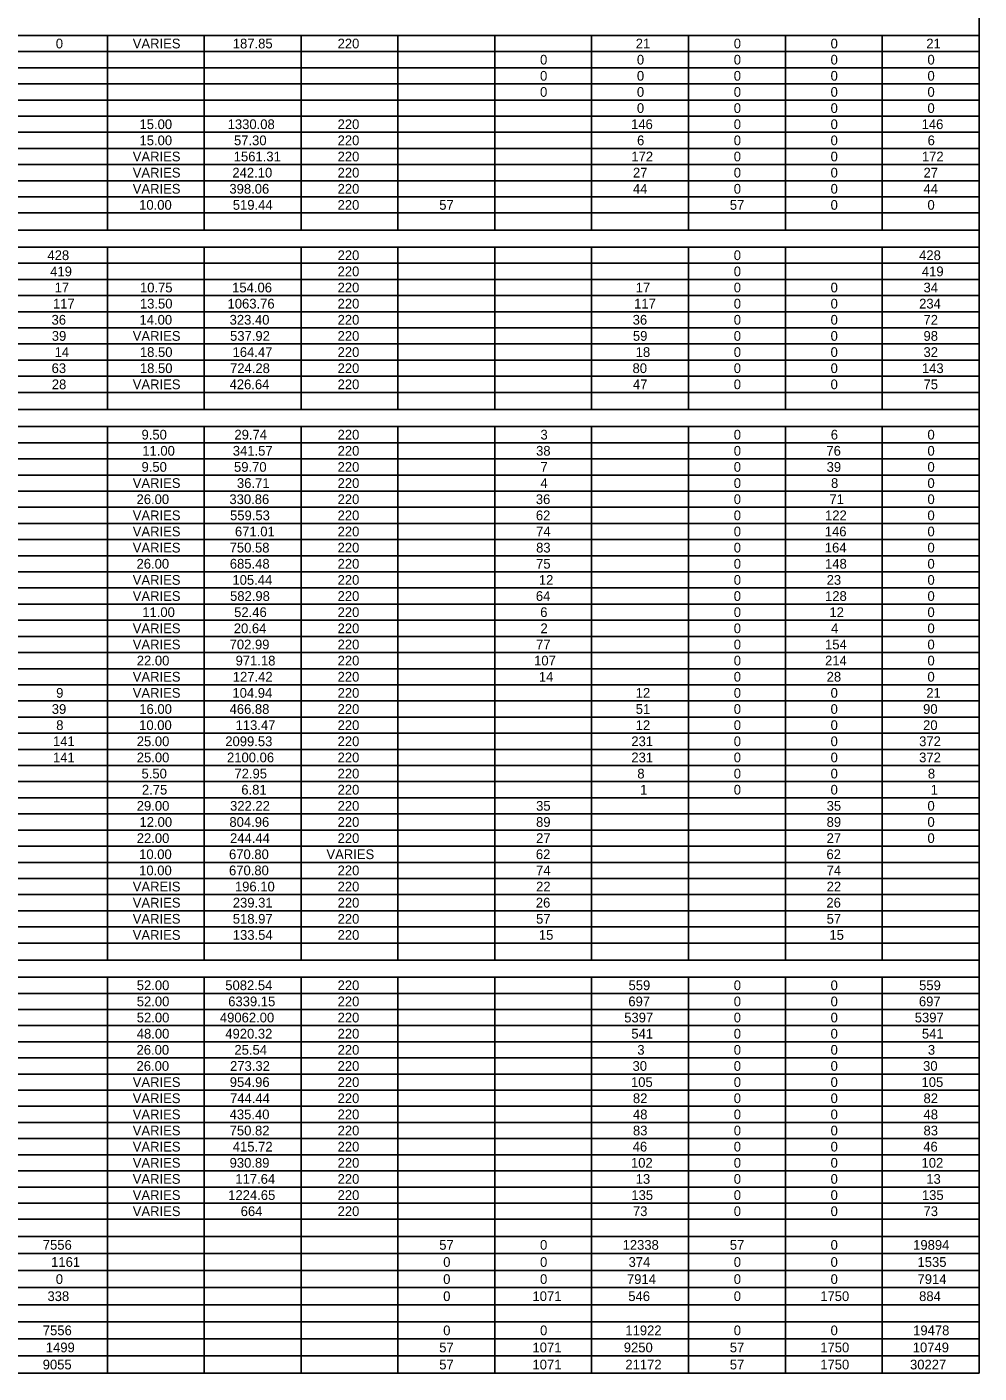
# Model space of a CAD drawing. Extents: x 1226590 to 1228573, y 151304 to 154224.
# Drawn here: x 1228084 to 1228573, y 152628 to 153319 of the extents above; entities that cross this region are included whole.
import ezdxf

# ---------------------------------------------------------------- set-up
doc = ezdxf.new("R2010")
doc.units = 0
doc.layers.add('R_Dimension', color=7, linetype='Continuous')

msp = doc.modelspace()

# ---------------------------------------------------------------- linework, layer by layer
at = {"layer": 'R_Dimension'}
for p, q in [((1228572.93, 152627.62), (1228572.93, 154214.43)), ((1226590.27, 153314.5), (1228572.93, 153314.5)), ((1228125.41, 153214.57), (1228125.41, 153314.5)), ((1228175.13, 153214.57), (1228175.13, 153314.5)), ((1228224.86, 153214.57), (1228224.86, 153314.5)), ((1228274.58, 153214.57), (1228274.58, 153314.5)), ((1228324.31, 153214.57), (1228324.31, 153314.5)), ((1228374.03, 153214.57), (1228374.03, 153314.5)), ((1228423.76, 153214.57), (1228423.76, 153314.5)), ((1228473.48, 153214.57), (1228473.48, 153314.5)), ((1228523.21, 153214.57), (1228523.21, 153314.5)), ((1226590.27, 153306.22), (1228572.93, 153306.22)), ((1226590.27, 153297.93), (1228572.93, 153297.93)), ((1226590.27, 153289.64), (1228572.93, 153289.64)), ((1226590.27, 153281.35), (1228572.93, 153281.35)), ((1226590.27, 153273.07), (1228572.93, 153273.07)), ((1226590.27, 153264.78), (1228572.93, 153264.78)), ((1226590.27, 153256.49), (1228572.93, 153256.49)), ((1226590.27, 153248.2), (1228572.93, 153248.2)), ((1226590.27, 153239.92), (1228572.93, 153239.92)), ((1226590.27, 153231.63), (1228572.93, 153231.63)), ((1226590.27, 153223.34), (1228572.93, 153223.34)), ((1226590.27, 153214.57), (1228572.93, 153214.57)), ((1226590.27, 153205.79), (1228572.93, 153205.79)), ((1228125.41, 153122.43), (1228125.41, 153205.79)), ((1228175.13, 153122.43), (1228175.13, 153205.79)), ((1228224.86, 153122.43), (1228224.86, 153205.79)), ((1228274.58, 153122.43), (1228274.58, 153205.79)), ((1228324.31, 153122.43), (1228324.31, 153205.79)), ((1228374.03, 153122.43), (1228374.03, 153205.79)), ((1228423.76, 153122.43), (1228423.76, 153205.79)), ((1228473.48, 153122.43), (1228473.48, 153205.79)), ((1228523.21, 153122.43), (1228523.21, 153205.79)), ((1226590.27, 153197.5), (1228572.93, 153197.5)), ((1226590.27, 153189.22), (1228572.93, 153189.22)), ((1226590.27, 153180.93), (1228572.93, 153180.93)), ((1226590.27, 153172.64), (1228572.93, 153172.64)), ((1226590.27, 153164.35), (1228572.93, 153164.35)), ((1226590.27, 153156.07), (1228572.93, 153156.07)), ((1226590.27, 153147.78), (1228572.93, 153147.78)), ((1226590.27, 153139.49), (1228572.93, 153139.49)), ((1226590.27, 153131.2), (1228572.93, 153131.2)), ((1226590.27, 153122.43), (1228572.93, 153122.43)), ((1226590.27, 153113.65), (1228572.93, 153113.65)), ((1228125.41, 152839.68), (1228125.41, 153113.65)), ((1228175.13, 152839.68), (1228175.13, 153113.65)), ((1228224.86, 152839.68), (1228224.86, 153113.65)), ((1228274.58, 152839.68), (1228274.58, 153113.65)), ((1228324.31, 152839.68), (1228324.31, 153113.65)), ((1228374.03, 152839.68), (1228374.03, 153113.65)), ((1228423.76, 152839.68), (1228423.76, 153113.65)), ((1228473.48, 152839.68), (1228473.48, 153113.65)), ((1228523.21, 152839.68), (1228523.21, 153113.65)), ((1226590.27, 153105.37), (1228572.93, 153105.37)), ((1226590.27, 153097.08), (1228572.93, 153097.08)), ((1226590.27, 153088.79), (1228572.93, 153088.79)), ((1226590.27, 153080.5), (1228572.93, 153080.5)), ((1226590.27, 153072.22), (1228572.93, 153072.22)), ((1226590.27, 153063.93), (1228572.93, 153063.93)), ((1226590.27, 153055.64), (1228572.93, 153055.64)), ((1226590.27, 153047.35), (1228572.93, 153047.35)), ((1226590.27, 153039.07), (1228572.93, 153039.07)), ((1226590.27, 153030.78), (1228572.93, 153030.78)), ((1226590.27, 153022.49), (1228572.93, 153022.49)), ((1226590.27, 153014.2), (1228572.93, 153014.2)), ((1226590.27, 153005.92), (1228572.93, 153005.92)), ((1226590.27, 152997.63), (1228572.93, 152997.63)), ((1226590.27, 152989.34), (1228572.93, 152989.34)), ((1226590.27, 152981.05), (1228572.93, 152981.05)), ((1226590.27, 152972.77), (1228572.93, 152972.77)), ((1226590.27, 152964.48), (1228572.93, 152964.48)), ((1226590.27, 152956.19), (1228572.93, 152956.19)), ((1226590.27, 152947.9), (1228572.93, 152947.9)), ((1226590.27, 152939.62), (1228572.93, 152939.62)), ((1226590.27, 152931.33), (1228572.93, 152931.33)), ((1226590.27, 152923.04), (1228572.93, 152923.04)), ((1226590.27, 152914.75), (1228572.93, 152914.75)), ((1226590.27, 152906.47), (1228572.93, 152906.47)), ((1226590.27, 152898.18), (1228572.93, 152898.18)), ((1226590.27, 152889.89), (1228572.93, 152889.89)), ((1226590.27, 152881.6), (1228572.93, 152881.6)), ((1226590.27, 152873.32), (1228572.93, 152873.32)), ((1226590.27, 152865.03), (1228572.93, 152865.03)), ((1226590.27, 152856.74), (1228572.93, 152856.74)), ((1226590.27, 152848.45), (1228572.93, 152848.45)), ((1226590.27, 152839.68), (1228572.93, 152839.68)), ((1226590.27, 152830.9), (1228572.93, 152830.9)), ((1228125.41, 152627.62), (1228125.41, 152830.9)), ((1228175.13, 152627.62), (1228175.13, 152830.9)), ((1228224.86, 152627.62), (1228224.86, 152830.9)), ((1228274.58, 152627.62), (1228274.58, 152830.9)), ((1228324.31, 152627.62), (1228324.31, 152830.9)), ((1228374.03, 152627.62), (1228374.03, 152830.9)), ((1228423.76, 152627.62), (1228423.76, 152830.9)), ((1228473.48, 152627.62), (1228473.48, 152830.9)), ((1228523.21, 152627.62), (1228523.21, 152830.9)), ((1226590.27, 152822.62), (1228572.93, 152822.62)), ((1226590.27, 152814.33), (1228572.93, 152814.33)), ((1226590.27, 152806.04), (1228572.93, 152806.04)), ((1226590.27, 152797.75), (1228572.93, 152797.75)), ((1226590.27, 152789.47), (1228572.93, 152789.47)), ((1226590.27, 152781.18), (1228572.93, 152781.18)), ((1226590.27, 152772.89), (1228572.93, 152772.89)), ((1226590.27, 152764.6), (1228572.93, 152764.6)), ((1226590.27, 152756.32), (1228572.93, 152756.32)), ((1226590.27, 152748.03), (1228572.93, 152748.03)), ((1226590.27, 152739.74), (1228572.93, 152739.74)), ((1226590.27, 152731.45), (1228572.93, 152731.45)), ((1226590.27, 152723.17), (1228572.93, 152723.17)), ((1226590.27, 152714.88), (1228572.93, 152714.88)), ((1226590.27, 152706.59), (1228572.93, 152706.59)), ((1226590.27, 152697.82), (1228572.93, 152697.82)), ((1226590.27, 152689.04), (1228572.93, 152689.04)), ((1226590.27, 152680.27), (1228572.93, 152680.27)), ((1226590.27, 152671.49), (1228572.93, 152671.49)), ((1226590.27, 152662.72), (1228572.93, 152662.72)), ((1226590.27, 152653.94), (1228572.93, 152653.94)), ((1226590.27, 152645.17), (1228572.93, 152645.17)), ((1226590.27, 152636.39), (1228572.93, 152636.39)), ((1226590.27, 152627.62), (1228572.93, 152627.62))]:
    msp.add_line(p, q, dxfattribs=at)

# ---------------------------------------------------------------- texts
for s, p in [('0', (1228098.91, 153307.86)), ('VARIES', (1228138.42, 153307.86)), ('187.85', (1228189.8, 153307.86)), ('220', (1228243.6, 153307.86)), ('21', (1228396.65, 153307.86)), ('0', (1228446.99, 153307.86)), ('0', (1228496.71, 153307.86)), ('21', (1228545.83, 153307.86)), ('0', (1228347.54, 153299.57)), ('0', (1228397.26, 153299.57)), ('0', (1228446.99, 153299.57)), ('0', (1228496.71, 153299.57)), ('0', (1228546.44, 153299.57)), ('0', (1228347.54, 153291.29)), ('0', (1228397.26, 153291.29)), ('0', (1228446.99, 153291.29)), ('0', (1228496.71, 153291.29)), ('0', (1228546.44, 153291.29)), ('0', (1228347.54, 153283)), ('0', (1228397.26, 153283)), ('0', (1228446.99, 153283)), ('0', (1228496.71, 153283)), ('0', (1228546.44, 153283)), ('0', (1228397.26, 153274.71)), ('0', (1228446.99, 153274.71)), ('0', (1228496.71, 153274.71)), ('0', (1228546.44, 153274.71)), ('15.00', (1228141.9, 153266.42)), ('1330.08', (1228187.16, 153266.42)), ('220', (1228243.6, 153266.42)), ('146', (1228394.27, 153266.42)), ('0', (1228446.99, 153266.42)), ('0', (1228496.71, 153266.42)), ('146', (1228543.44, 153266.42)), ('15.00', (1228141.9, 153258.14)), ('57.30', (1228190.41, 153258.14)), ('220', (1228243.6, 153258.14)), ('6', (1228397.34, 153258.14)), ('0', (1228446.99, 153258.14)), ('0', (1228496.71, 153258.14)), ('6', (1228546.52, 153258.14)), ('VARIES', (1228138.42, 153249.85)), ('1561.31', (1228190.27, 153249.85)), ('220', (1228243.6, 153249.85)), ('172', (1228394.41, 153249.85)), ('0', (1228446.99, 153249.85)), ('0', (1228496.71, 153249.85)), ('172', (1228543.58, 153249.85)), ('VARIES', (1228138.42, 153241.56)), ('242.10', (1228189.58, 153241.56)), ('220', (1228243.6, 153241.56)), ('27', (1228395.23, 153241.56)), ('0', (1228446.99, 153241.56)), ('0', (1228496.71, 153241.56)), ('27', (1228544.41, 153241.56)), ('VARIES', (1228138.42, 153233.27)), ('398.06', (1228188.05, 153233.27)), ('220', (1228243.6, 153233.27)), ('44', (1228395.23, 153233.27)), ('0', (1228446.99, 153233.27)), ('0', (1228496.71, 153233.27)), ('44', (1228544.41, 153233.27)), ('10.00', (1228141.71, 153224.99)), ('519.44', (1228189.8, 153224.99)), ('220', (1228243.6, 153224.99)), ('57', (1228295.78, 153224.99)), ('57', (1228444.96, 153224.99)), ('0', (1228496.71, 153224.99)), ('0', (1228546.44, 153224.99)), ('428', (1228094.64, 153199.15)), ('220', (1228243.6, 153199.15)), ('0', (1228446.99, 153199.15)), ('428', (1228542.16, 153199.15)), ('419', (1228096.04, 153190.86)), ('220', (1228243.6, 153190.86)), ('0', (1228446.99, 153190.86)), ('419', (1228543.56, 153190.86)), ('17', (1228098.3, 153182.57)), ('10.75', (1228142.12, 153182.57)), ('154.06', (1228189.46, 153182.57)), ('220', (1228243.6, 153182.57)), ('17', (1228396.65, 153182.57)), ('0', (1228446.99, 153182.57)), ('0', (1228496.71, 153182.57)), ('34', (1228544.41, 153182.57)), ('117', (1228097.47, 153174.29)), ('13.50', (1228142.1, 153174.29)), ('1063.76', (1228187.1, 153174.29)), ('220', (1228243.6, 153174.29)), ('117', (1228395.82, 153174.29)), ('0', (1228446.99, 153174.29)), ('0', (1228496.71, 153174.29)), ('234', (1228542.16, 153174.29)), ('36', (1228096.75, 153166)), ('14.00', (1228141.9, 153166)), ('323.40', (1228188.16, 153166)), ('220', (1228243.6, 153166)), ('36', (1228395.1, 153166)), ('0', (1228446.99, 153166)), ('0', (1228496.71, 153166)), ('72', (1228544.41, 153166)), ('39', (1228096.86, 153157.71)), ('VARIES', (1228138.42, 153157.71)), ('537.92', (1228188.38, 153157.71)), ('220', (1228243.6, 153157.71)), ('59', (1228395.21, 153157.71)), ('0', (1228446.99, 153157.71)), ('0', (1228496.71, 153157.71)), ('98', (1228544.41, 153157.71)), ('14', (1228098.3, 153149.42)), ('18.50', (1228142.1, 153149.42)), ('164.47', (1228189.68, 153149.42)), ('220', (1228243.6, 153149.42)), ('18', (1228396.65, 153149.42)), ('0', (1228446.99, 153149.42)), ('0', (1228496.71, 153149.42)), ('32', (1228544.41, 153149.42)), ('63', (1228096.77, 153141.14)), ('18.50', (1228142.1, 153141.14)), ('724.28', (1228188.38, 153141.14)), ('220', (1228243.6, 153141.14)), ('80', (1228395.02, 153141.14)), ('0', (1228446.99, 153141.14)), ('0', (1228496.71, 153141.14)), ('143', (1228543.58, 153141.14)), ('28', (1228096.88, 153132.85)), ('VARIES', (1228138.42, 153132.85)), ('426.64', (1228188.14, 153132.85)), ('220', (1228243.6, 153132.85)), ('47', (1228395.23, 153132.85)), ('0', (1228446.99, 153132.85)), ('0', (1228496.71, 153132.85)), ('75', (1228544.41, 153132.85)), ('9.50', (1228142.93, 153107.01)), ('29.74', (1228190.63, 153107.01)), ('220', (1228243.6, 153107.01)), ('3', (1228347.75, 153107.01)), ('0', (1228446.99, 153107.01)), ('6', (1228496.79, 153107.01)), ('0', (1228546.44, 153107.01)), ('11.00', (1228143.32, 153098.72)), ('341.57', (1228189.8, 153098.72)), ('220', (1228243.6, 153098.72)), ('38', (1228345.51, 153098.72)), ('0', (1228446.99, 153098.72)), ('76', (1228494.55, 153098.72)), ('0', (1228546.44, 153098.72)), ('9.50', (1228142.93, 153090.44)), ('59.70', (1228190.41, 153090.44)), ('220', (1228243.6, 153090.44)), ('7', (1228347.75, 153090.44)), ('0', (1228446.99, 153090.44)), ('39', (1228494.66, 153090.44)), ('0', (1228546.44, 153090.44)), ('VARIES', (1228138.42, 153082.15)), ('36.71', (1228191.92, 153082.15)), ('220', (1228243.6, 153082.15)), ('4', (1228347.75, 153082.15)), ('0', (1228446.99, 153082.15)), ('8', (1228496.93, 153082.15)), ('0', (1228546.44, 153082.15)), ('26.00', (1228140.37, 153073.86)), ('330.86', (1228188.05, 153073.86)), ('220', (1228243.6, 153073.86)), ('36', (1228345.37, 153073.86)), ('0', (1228446.99, 153073.86)), ('71', (1228496.1, 153073.86)), ('0', (1228546.44, 153073.86)), ('VARIES', (1228138.42, 153065.57)), ('559.53', (1228188.38, 153065.57)), ('220', (1228243.6, 153065.57)), ('62', (1228345.39, 153065.57)), ('0', (1228446.99, 153065.57)), ('122', (1228493.86, 153065.57)), ('0', (1228546.44, 153065.57)), ('VARIES', (1228138.42, 153057.29)), ('671.01', (1228190.9, 153057.29)), ('220', (1228243.6, 153057.29)), ('74', (1228345.51, 153057.29)), ('0', (1228446.99, 153057.29)), ('146', (1228493.72, 153057.29)), ('0', (1228546.44, 153057.29)), ('VARIES', (1228138.42, 153049)), ('750.58', (1228188.18, 153049)), ('220', (1228243.6, 153049)), ('83', (1228345.51, 153049)), ('0', (1228446.99, 153049)), ('164', (1228493.74, 153049)), ('0', (1228546.44, 153049)), ('26.00', (1228140.37, 153040.71)), ('685.48', (1228188.26, 153040.71)), ('220', (1228243.6, 153040.71)), ('75', (1228345.51, 153040.71)), ('0', (1228446.99, 153040.71)), ('148', (1228493.86, 153040.71)), ('0', (1228546.44, 153040.71)), ('VARIES', (1228138.42, 153032.42)), ('105.44', (1228189.6, 153032.42)), ('220', (1228243.6, 153032.42)), ('12', (1228346.93, 153032.42)), ('0', (1228446.99, 153032.42)), ('23', (1228494.68, 153032.42)), ('0', (1228546.44, 153032.42)), ('VARIES', (1228138.42, 153024.14)), ('582.98', (1228188.38, 153024.14)), ('220', (1228243.6, 153024.14)), ('64', (1228345.39, 153024.14)), ('0', (1228446.99, 153024.14)), ('128', (1228493.86, 153024.14)), ('0', (1228546.44, 153024.14)), ('11.00', (1228143.32, 153015.85)), ('52.46', (1228190.49, 153015.85)), ('220', (1228243.6, 153015.85)), ('6', (1228347.62, 153015.85)), ('0', (1228446.99, 153015.85)), ('12', (1228496.1, 153015.85)), ('0', (1228546.44, 153015.85)), ('VARIES', (1228138.42, 153007.56)), ('20.64', (1228190.31, 153007.56)), ('220', (1228243.6, 153007.56)), ('2', (1228347.75, 153007.56)), ('0', (1228446.99, 153007.56)), ('4', (1228496.93, 153007.56)), ('0', (1228546.44, 153007.56)), ('VARIES', (1228138.42, 152999.27)), ('702.99', (1228188.16, 152999.27)), ('220', (1228243.6, 152999.27)), ('77', (1228345.51, 152999.27)), ('0', (1228446.99, 152999.27)), ('154', (1228493.86, 152999.27)), ('0', (1228546.44, 152999.27)), ('22.00', (1228140.49, 152990.99)), ('971.18', (1228191.22, 152990.99)), ('220', (1228243.6, 152990.99)), ('107', (1228344.49, 152990.99)), ('0', (1228446.99, 152990.99)), ('214', (1228493.86, 152990.99)), ('0', (1228546.44, 152990.99)), ('VARIES', (1228138.42, 152982.7)), ('127.42', (1228189.8, 152982.7)), ('220', (1228243.6, 152982.7)), ('14', (1228346.93, 152982.7)), ('0', (1228446.99, 152982.7)), ('28', (1228494.68, 152982.7)), ('0', (1228546.44, 152982.7)), ('9', (1228099.11, 152974.41)), ('VARIES', (1228138.42, 152974.41)), ('104.94', (1228189.6, 152974.41)), ('220', (1228243.6, 152974.41)), ('12', (1228396.65, 152974.41)), ('0', (1228446.99, 152974.41)), ('0', (1228496.71, 152974.41)), ('21', (1228545.83, 152974.41)), ('39', (1228096.86, 152966.12)), ('16.00', (1228141.79, 152966.12)), ('466.88', (1228188.14, 152966.12)), ('220', (1228243.6, 152966.12)), ('51', (1228396.65, 152966.12)), ('0', (1228446.99, 152966.12)), ('0', (1228496.71, 152966.12)), ('90', (1228544.19, 152966.12)), ('8', (1228099.13, 152957.84)), ('10.00', (1228141.71, 152957.84)), ('113.47', (1228191.22, 152957.84)), ('220', (1228243.6, 152957.84)), ('12', (1228396.65, 152957.84)), ('0', (1228446.99, 152957.84)), ('0', (1228496.71, 152957.84)), ('20', (1228544.19, 152957.84)), ('141', (1228097.47, 152949.55)), ('25.00', (1228140.49, 152949.55)), ('2099.53', (1228185.94, 152949.55)), ('220', (1228243.6, 152949.55)), ('231', (1228394.41, 152949.55)), ('0', (1228446.99, 152949.55)), ('0', (1228496.71, 152949.55)), ('372', (1228542.16, 152949.55)), ('141', (1228097.47, 152941.26)), ('25.00', (1228140.49, 152941.26)), ('2100.06', (1228186.83, 152941.26)), ('220', (1228243.6, 152941.26)), ('231', (1228394.41, 152941.26)), ('0', (1228446.99, 152941.26)), ('0', (1228496.71, 152941.26)), ('372', (1228542.16, 152941.26)), ('5.50', (1228142.93, 152932.97)), ('72.95', (1228190.63, 152932.97)), ('220', (1228243.6, 152932.97)), ('8', (1228397.48, 152932.97)), ('0', (1228446.99, 152932.97)), ('0', (1228496.71, 152932.97)), ('8', (1228546.65, 152932.97)), ('2.75', (1228143.14, 152924.69)), ('6.81', (1228194.17, 152924.69)), ('220', (1228243.6, 152924.69)), ('1', (1228398.9, 152924.69)), ('0', (1228446.99, 152924.69)), ('0', (1228496.71, 152924.69)), ('1', (1228548.07, 152924.69)), ('29.00', (1228140.49, 152916.4)), ('322.22', (1228188.38, 152916.4)), ('220', (1228243.6, 152916.4)), ('35', (1228345.51, 152916.4)), ('35', (1228494.68, 152916.4)), ('0', (1228546.44, 152916.4)), ('12.00', (1228141.9, 152908.11)), ('804.96', (1228188.05, 152908.11)), ('220', (1228243.6, 152908.11)), ('89', (1228345.49, 152908.11)), ('89', (1228494.66, 152908.11)), ('0', (1228546.44, 152908.11)), ('22.00', (1228140.49, 152899.82)), ('244.44', (1228188.38, 152899.82)), ('220', (1228243.6, 152899.82)), ('27', (1228345.51, 152899.82)), ('27', (1228494.68, 152899.82)), ('0', (1228546.44, 152899.82)), ('10.00', (1228141.71, 152891.54)), ('670.80', (1228187.85, 152891.54)), ('VARIES', (1228237.87, 152891.54)), ('62', (1228345.39, 152891.54)), ('62', (1228494.57, 152891.54)), ('10.00', (1228141.71, 152883.25)), ('670.80', (1228187.85, 152883.25)), ('220', (1228243.6, 152883.25)), ('74', (1228345.51, 152883.25)), ('74', (1228494.68, 152883.25)), ('VAREIS', (1228138.42, 152874.96)), ('196.10', (1228190.88, 152874.96)), ('220', (1228243.6, 152874.96)), ('22', (1228345.51, 152874.96)), ('22', (1228494.68, 152874.96)), ('VARIES', (1228138.42, 152866.67)), ('239.31', (1228189.8, 152866.67)), ('220', (1228243.6, 152866.67)), ('26', (1228345.37, 152866.67)), ('26', (1228494.55, 152866.67)), ('VARIES', (1228138.42, 152858.39)), ('518.97', (1228189.8, 152858.39)), ('220', (1228243.6, 152858.39)), ('57', (1228345.51, 152858.39)), ('57', (1228494.68, 152858.39)), ('VARIES', (1228138.42, 152850.1)), ('133.54', (1228189.8, 152850.1)), ('220', (1228243.6, 152850.1)), ('15', (1228346.93, 152850.1)), ('15', (1228496.1, 152850.1)), ('52.00', (1228140.49, 152824.26)), ('5082.54', (1228185.94, 152824.26)), ('220', (1228243.6, 152824.26)), ('559', (1228392.97, 152824.26)), ('0', (1228446.99, 152824.26)), ('0', (1228496.71, 152824.26)), ('559', (1228542.14, 152824.26)), ('52.00', (1228140.49, 152815.97)), ('6339.15', (1228187.44, 152815.97)), ('220', (1228243.6, 152815.97)), ('697', (1228392.87, 152815.97)), ('0', (1228446.99, 152815.97)), ('0', (1228496.71, 152815.97)), ('697', (1228542.05, 152815.97)), ('52.00', (1228140.49, 152807.69)), ('49062.00', (1228183.16, 152807.69)), ('220', (1228243.6, 152807.69)), ('5397', (1228390.75, 152807.69)), ('0', (1228446.99, 152807.69)), ('0', (1228496.71, 152807.69)), ('5397', (1228539.92, 152807.69)), ('48.00', (1228140.49, 152799.4)), ('4920.32', (1228185.94, 152799.4)), ('220', (1228243.6, 152799.4)), ('541', (1228394.41, 152799.4)), ('0', (1228446.99, 152799.4)), ('0', (1228496.71, 152799.4)), ('541', (1228543.58, 152799.4)), ('26.00', (1228140.37, 152791.11)), ('25.54', (1228190.63, 152791.11)), ('220', (1228243.6, 152791.11)), ('3', (1228397.48, 152791.11)), ('0', (1228446.99, 152791.11)), ('0', (1228496.71, 152791.11)), ('3', (1228546.65, 152791.11)), ('26.00', (1228140.37, 152782.82)), ('273.32', (1228188.38, 152782.82)), ('220', (1228243.6, 152782.82)), ('30', (1228395.02, 152782.82)), ('0', (1228446.99, 152782.82)), ('0', (1228496.71, 152782.82)), ('30', (1228544.19, 152782.82)), ('VARIES', (1228138.42, 152774.54)), ('954.96', (1228188.24, 152774.54)), ('220', (1228243.6, 152774.54)), ('105', (1228394.21, 152774.54)), ('0', (1228446.99, 152774.54)), ('0', (1228496.71, 152774.54)), ('105', (1228543.39, 152774.54)), ('VARIES', (1228138.42, 152766.25)), ('744.44', (1228188.38, 152766.25)), ('220', (1228243.6, 152766.25)), ('82', (1228395.23, 152766.25)), ('0', (1228446.99, 152766.25)), ('0', (1228496.71, 152766.25)), ('82', (1228544.41, 152766.25)), ('VARIES', (1228138.42, 152757.96)), ('435.40', (1228188.16, 152757.96)), ('220', (1228243.6, 152757.96)), ('48', (1228395.23, 152757.96)), ('0', (1228446.99, 152757.96)), ('0', (1228496.71, 152757.96)), ('48', (1228544.41, 152757.96)), ('VARIES', (1228138.42, 152749.67)), ('750.82', (1228188.18, 152749.67)), ('220', (1228243.6, 152749.67)), ('83', (1228395.23, 152749.67)), ('0', (1228446.99, 152749.67)), ('0', (1228496.71, 152749.67)), ('83', (1228544.41, 152749.67)), ('VARIES', (1228138.42, 152741.39)), ('415.72', (1228189.8, 152741.39)), ('220', (1228243.6, 152741.39)), ('46', (1228395.1, 152741.39)), ('0', (1228446.99, 152741.39)), ('0', (1228496.71, 152741.39)), ('46', (1228544.27, 152741.39)), ('VARIES', (1228138.42, 152733.1)), ('930.89', (1228188.16, 152733.1)), ('220', (1228243.6, 152733.1)), ('102', (1228394.21, 152733.1)), ('0', (1228446.99, 152733.1)), ('0', (1228496.71, 152733.1)), ('102', (1228543.39, 152733.1)), ('VARIES', (1228138.42, 152724.81)), ('117.64', (1228191.1, 152724.81)), ('220', (1228243.6, 152724.81)), ('13', (1228396.65, 152724.81)), ('0', (1228446.99, 152724.81)), ('0', (1228496.71, 152724.81)), ('13', (1228545.83, 152724.81)), ('VARIES', (1228138.42, 152716.52)), ('1224.65', (1228187.44, 152716.52)), ('220', (1228243.6, 152716.52)), ('135', (1228394.41, 152716.52)), ('0', (1228446.99, 152716.52)), ('0', (1228496.71, 152716.52)), ('135', (1228543.58, 152716.52)), ('VARIES', (1228138.42, 152708.24)), ('664', (1228193.85, 152708.24)), ('220', (1228243.6, 152708.24)), ('73', (1228395.23, 152708.24)), ('0', (1228446.99, 152708.24)), ('0', (1228496.71, 152708.24)), ('73', (1228544.41, 152708.24)), ('7556', (1228092.26, 152690.93)), ('57', (1228295.78, 152690.93)), ('0', (1228347.54, 152690.93)), ('12338', (1228389.92, 152690.93)), ('57', (1228444.96, 152690.93)), ('0', (1228496.71, 152690.93)), ('19894', (1228539.09, 152690.93)), ('1161', (1228096.53, 152682.15)), ('0', (1228297.81, 152682.15)), ('0', (1228347.54, 152682.15)), ('374', (1228392.99, 152682.15)), ('0', (1228446.99, 152682.15)), ('0', (1228496.71, 152682.15)), ('1535', (1228541.34, 152682.15)), ('0', (1228098.91, 152673.38)), ('0', (1228297.81, 152673.38)), ('0', (1228347.54, 152673.38)), ('7914', (1228392.16, 152673.38)), ('0', (1228446.99, 152673.38)), ('0', (1228496.71, 152673.38)), ('7914', (1228541.34, 152673.38)), ('338', (1228094.64, 152664.6)), ('0', (1228297.81, 152664.6)), ('1071', (1228343.66, 152664.6)), ('546', (1228392.85, 152664.6)), ('0', (1228446.99, 152664.6)), ('1750', (1228491.4, 152664.6)), ('884', (1228542.16, 152664.6)), ('7556', (1228092.26, 152647.05)), ('0', (1228297.81, 152647.05)), ('0', (1228347.54, 152647.05)), ('11922', (1228391.34, 152647.05)), ('0', (1228446.99, 152647.05)), ('0', (1228496.71, 152647.05)), ('19478', (1228539.09, 152647.05)), ('1499', (1228093.79, 152638.28)), ('57', (1228295.78, 152638.28)), ('1071', (1228343.66, 152638.28)), ('9250', (1228390.53, 152638.28)), ('57', (1228444.96, 152638.28)), ('1750', (1228491.4, 152638.28)), ('10749', (1228538.88, 152638.28)), ('9055', (1228092.2, 152629.5)), ('57', (1228295.78, 152629.5)), ('1071', (1228343.66, 152629.5)), ('21172', (1228391.34, 152629.5)), ('57', (1228444.96, 152629.5)), ('1750', (1228491.4, 152629.5)), ('30227', (1228537.48, 152629.5))]:
    msp.add_text(s, height=5, dxfattribs=at).set_placement(p)

doc.saveas('drawing.dxf')
